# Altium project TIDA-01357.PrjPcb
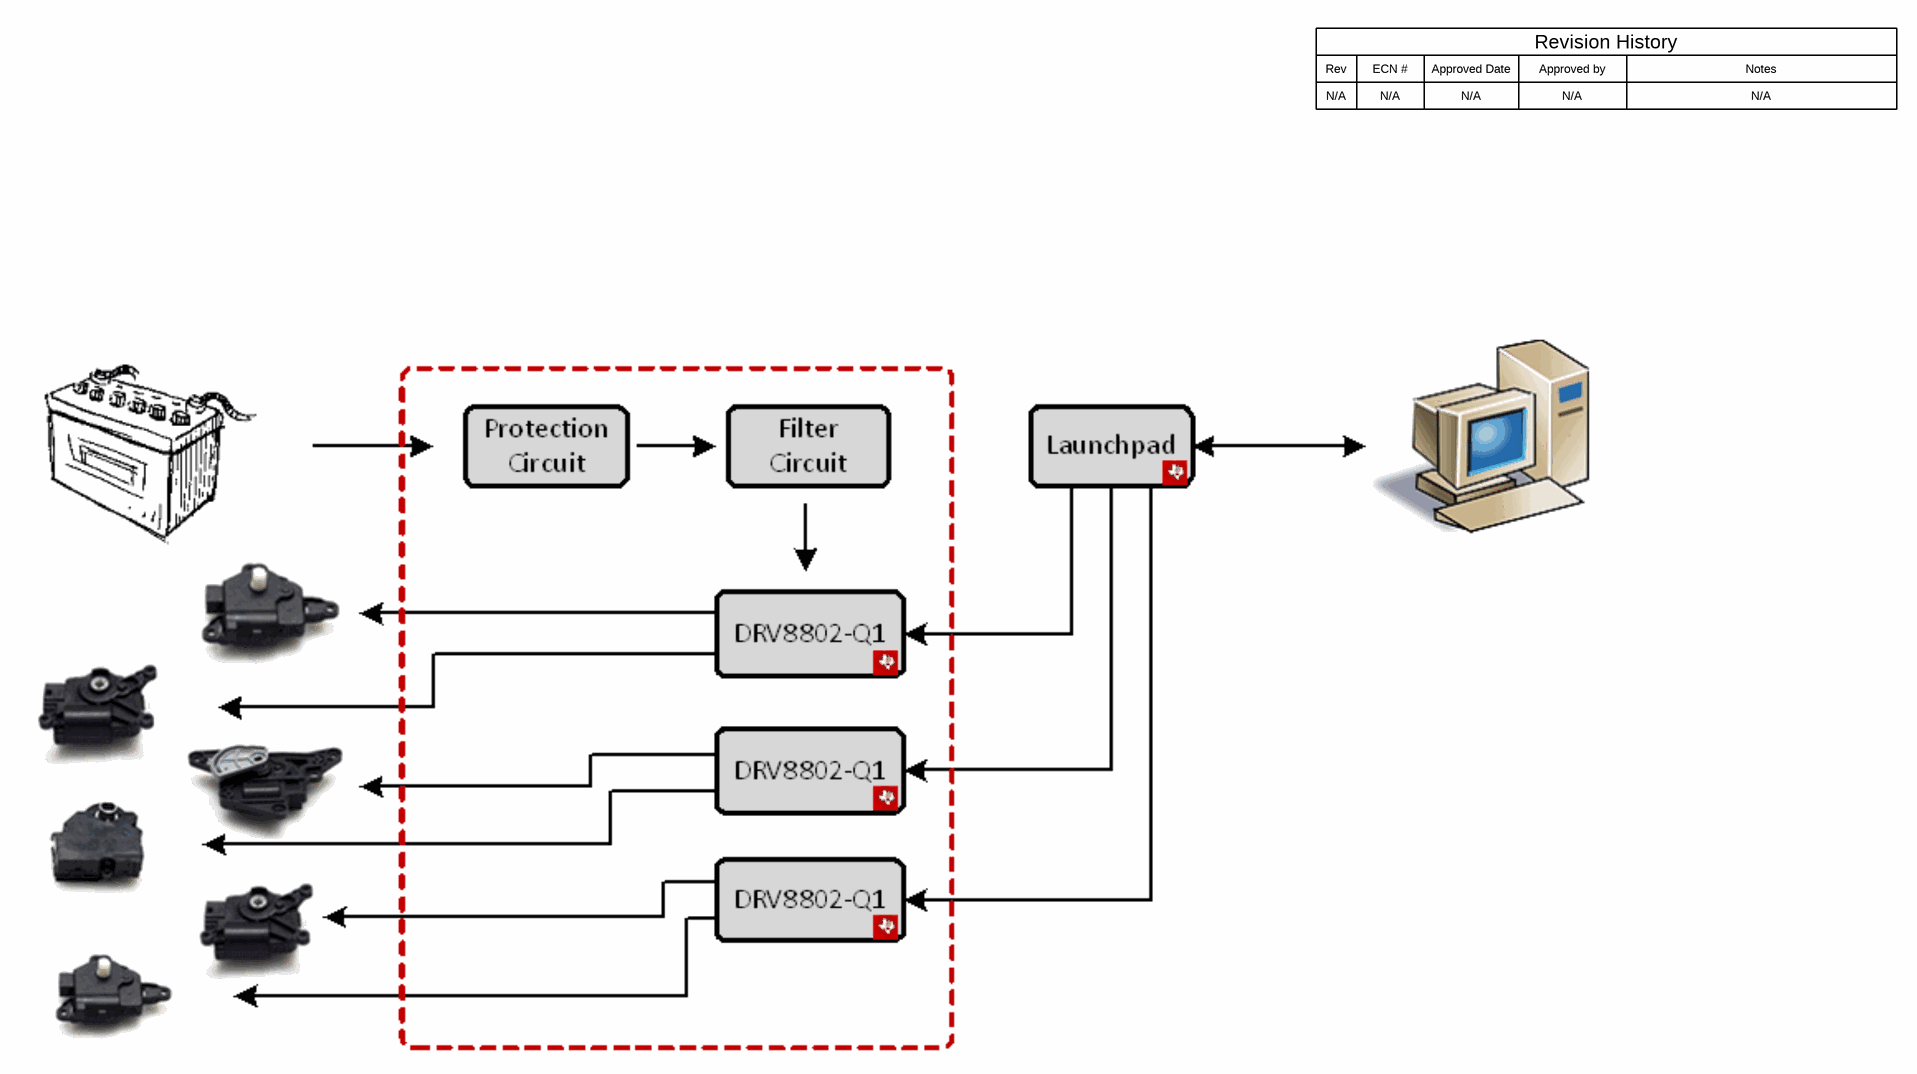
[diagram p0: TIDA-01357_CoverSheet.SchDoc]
CopyrightYear: 2016; PCB_Layout: Levan Bidzishvili; PCB_Rev: E1; PRJ_Customer: Public Release; PRJ_Engineer: Levan Bidzishvili; PRJ_Number: TIDA-01357; PRJ_Title: Automotive HVAC Multiple Flap Actuator / Damper Drivers; SCH_Rev: E1; TechSupport: http://www.ti.com/support; TID: TIDA-01357
3 sheets, 70 parts. Net scope: global (net labels, ports and power ports of the same name join across sheets).
Board file: TIDA-01357_PCB.PcbDoc
Sheets:
  TIDA-01357_CoverSheet.SchDoc
  TIDA-01357_BlankSheet.SchDoc
  TIDA-01357_EVM_Hardware.SchDoc

## Sheet TIDA-01357_CoverSheet.SchDoc
size 431 x 279 mm; Date: Not shown in title block; ApprovedBy: Not shown in title block; CheckedBy: Not shown in title block; Author: Not shown in title block; CompanyName: Not shown in title block; Engineer: Not shown in title block; Organization: Not shown in title block; Address1: Not shown in title block; Address2: Not shown in title block; Address3: Not shown in title block; Address4: Not shown in title block; DocumentNumber: 1; Revision: Use project parameter SCH_Rev; SheetNumber: 1; SheetTotal: 3; PageSetup: Record=PageOptions¦CenterHorizontal=True¦CenterVertical=True¦PrintScale=1.00¦XCorrection=1.00¦YCorrection=1.00¦PrintKind=0¦BorderSize=5000000¦LeftOffset=0¦BottomOffset=0¦Orientation=2¦PaperLength=1000¦PaperWidth=1000¦Scale=100¦PaperSource=15¦PrintQuality=600¦MediaType=1¦DitherType=10¦PaperKind=Letter¦PrintScaleMode=1

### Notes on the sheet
- Rev
- N/A
- ECN #
- Approved Date
- Approved by
- Revision History
- Notes

## Sheet TIDA-01357_BlankSheet.SchDoc
size 431 x 279 mm; Date: Not shown in title block; ApprovedBy: Not shown in title block; CheckedBy: Not shown in title block; Author: Not shown in title block; CompanyName: Not shown in title block; Engineer: Not shown in title block; Organization: Not shown in title block; Address1: Not shown in title block; Address2: Not shown in title block; Address3: Not shown in title block; Address4: Not shown in title block; DocumentNumber: 1; Revision: Use project parameter SCH_Rev; SheetNumber: 2; SheetTotal: 3; PageSetup: Record=PageOptions¦CenterHorizontal=True¦CenterVertical=True¦PrintScale=1.00¦XCorrection=1.00¦YCorrection=1.00¦PrintKind=0¦BorderSize=5000000¦LeftOffset=0¦BottomOffset=0¦Orientation=2¦PaperLength=1000¦PaperWidth=1000¦Scale=100¦PaperSource=15¦PrintQuality=600¦MediaType=1¦DitherType=10¦PaperKind=Letter¦PrintScaleMode=1
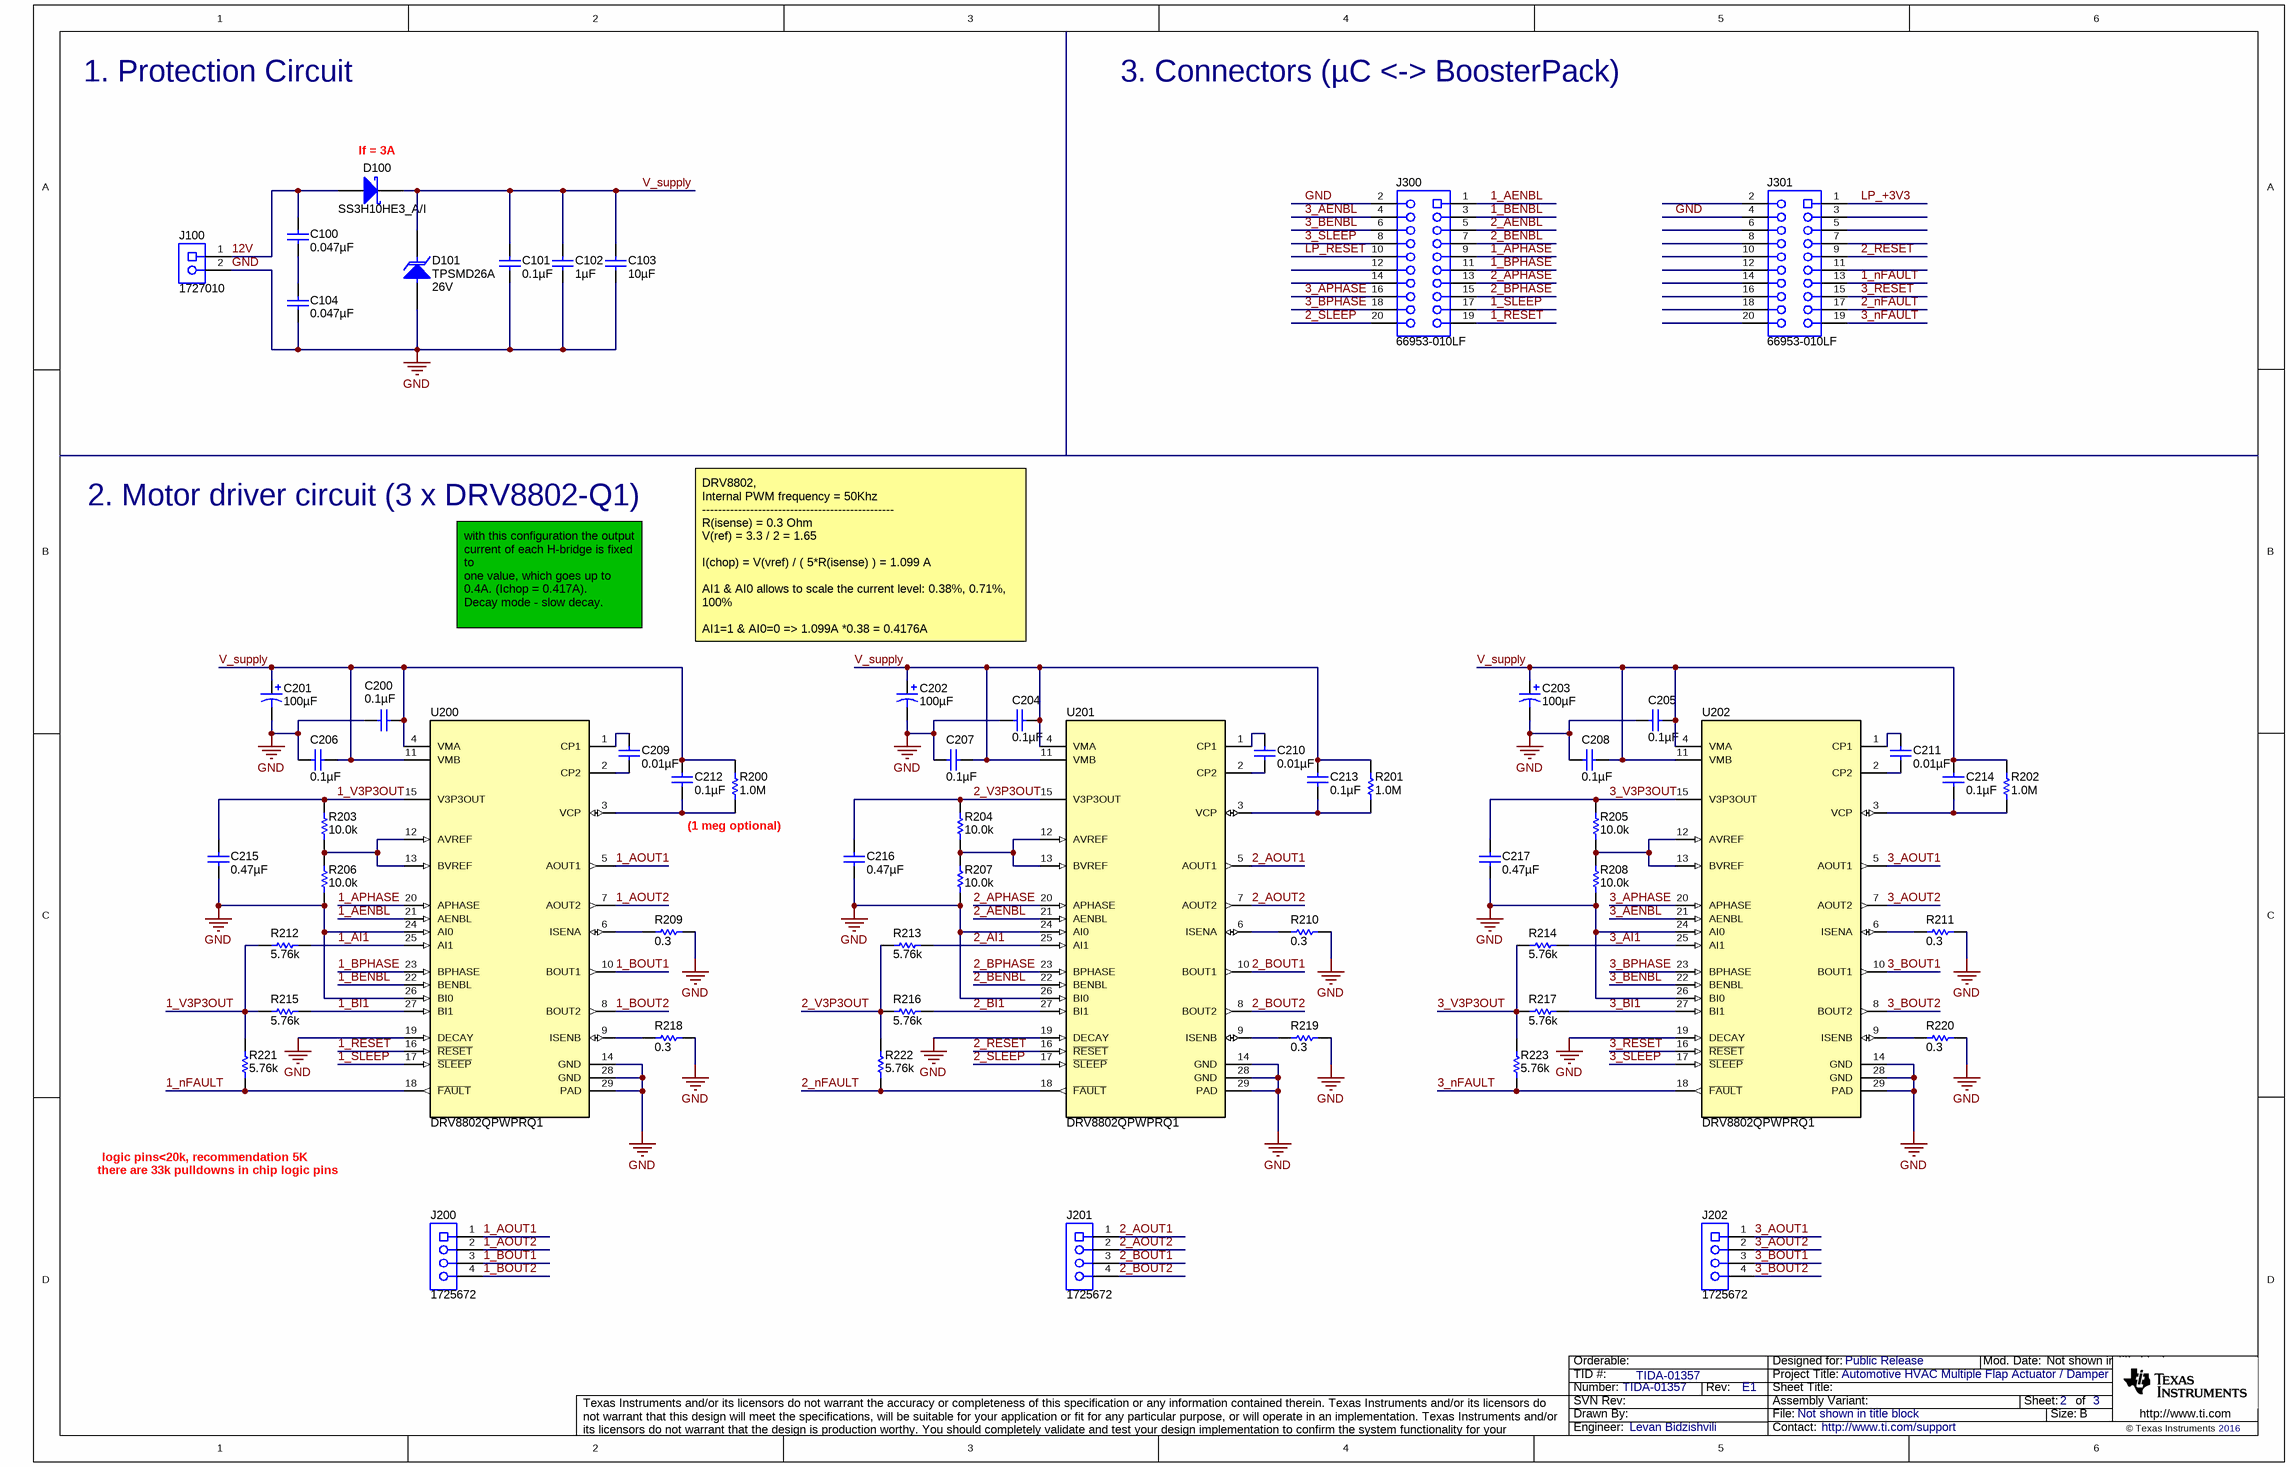
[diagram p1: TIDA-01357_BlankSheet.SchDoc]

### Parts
C100  ValueDisplayed: 0.047µF  [0805_HV]  (hidden comment: GCM21BR72A473KA37L)
C101  ValueDisplayed: 0.1µF  [0805_HV]  (hidden comment: GCM21BR71H104KA37K)
C102  ValueDisplayed: 1µF  [1206]  (hidden comment: GCM31MR71H105KA55L)
C103  ValueDisplayed: 10µF  [1206_190]  (hidden comment: CGA5L3X5R1H106K160AB)
C104  ValueDisplayed: 0.047µF  [0805_HV]  (hidden comment: GCM21BR72A473KA37L)
C200  ValueDisplayed: 0.1µF  [0805_HV]  (hidden comment: GCM21BR71H104KA37K)
C201  ValueDisplayed: 100µF  [Panasonic_D8]  (hidden comment: EEEFTH101XAP)
C202  ValueDisplayed: 100µF  [Panasonic_D8]  (hidden comment: EEEFTH101XAP)
C203  ValueDisplayed: 100µF  [Panasonic_D8]  (hidden comment: EEEFTH101XAP)
C204  ValueDisplayed: 0.1µF  [0805_HV]  (hidden comment: GCM21BR71H104KA37K)
C205  ValueDisplayed: 0.1µF  [0805_HV]  (hidden comment: GCM21BR71H104KA37K)
C206  ValueDisplayed: 0.1µF  [0805_HV]  (hidden comment: GCM21BR71H104KA37K)
C207  ValueDisplayed: 0.1µF  [0805_HV]  (hidden comment: GCM21BR71H104KA37K)
C208  ValueDisplayed: 0.1µF  [0805_HV]  (hidden comment: GCM21BR71H104KA37K)
C209  ValueDisplayed: 0.01µF  [0603]  (hidden comment: GCM188R71H103KA37D)
C210  ValueDisplayed: 0.01µF  [0603]  (hidden comment: GCM188R71H103KA37D)
C211  ValueDisplayed: 0.01µF  [0603]  (hidden comment: GCM188R71H103KA37D)
C212  ValueDisplayed: 0.1µF  [0603]  (hidden comment: GCM188R71C104KA37J)
C213  ValueDisplayed: 0.1µF  [0603]  (hidden comment: GCM188R71C104KA37J)
C214  ValueDisplayed: 0.1µF  [0603]  (hidden comment: GCM188R71C104KA37J)
C215  ValueDisplayed: 0.47µF  [0603]  (hidden comment: GCM188R71C474KA55D)
C216  ValueDisplayed: 0.47µF  [0603]  (hidden comment: GCM188R71C474KA55D)
C217  ValueDisplayed: 0.47µF  [0603]  (hidden comment: GCM188R71C474KA55D)
D100  SS3H10HE3_A/I  [SMC_265]
D101  TPSMD26A  value 26V  [SMC_265]
J100  1727010  [PhoenixConact_1727010]
J200  1725672  [Phoenix_1725672]
J201  1725672  [Phoenix_1725672]
J202  1725672  [Phoenix_1725672]
J300  66953-010LF  [FCI_66953-010LF]
J301  66953-010LF  [FCI_66953-010LF]
R200  ValueDisplayed: 1.0M  [0603]  (hidden comment: CRCW06031M00JNEA)
R201  ValueDisplayed: 1.0M  [0603]  (hidden comment: CRCW06031M00JNEA)
R202  ValueDisplayed: 1.0M  [0603]  (hidden comment: CRCW06031M00JNEA)
R203  ValueDisplayed: 10.0k  [0603]  (hidden comment: CRCW060310K0FKEA)
R204  ValueDisplayed: 10.0k  [0603]  (hidden comment: CRCW060310K0FKEA)
R205  ValueDisplayed: 10.0k  [0603]  (hidden comment: CRCW060310K0FKEA)
R206  ValueDisplayed: 10.0k  [0603]  (hidden comment: CRCW060310K0FKEA)
R207  ValueDisplayed: 10.0k  [0603]  (hidden comment: CRCW060310K0FKEA)
R208  ValueDisplayed: 10.0k  [0603]  (hidden comment: CRCW060310K0FKEA)
R209  ValueDisplayed: 0.3  [2010]  (hidden comment: CSR2010JTR300)
R210  ValueDisplayed: 0.3  [2010]  (hidden comment: CSR2010JTR300)
R211  ValueDisplayed: 0.3  [2010]  (hidden comment: CSR2010JTR300)
R212  ValueDisplayed: 5.76k  [0603]  (hidden comment: ERA-3AEB5761V)
R213  ValueDisplayed: 5.76k  [0603]  (hidden comment: ERA-3AEB5761V)
R214  ValueDisplayed: 5.76k  [0603]  (hidden comment: ERA-3AEB5761V)
R215  ValueDisplayed: 5.76k  [0603]  (hidden comment: ERA-3AEB5761V)
R216  ValueDisplayed: 5.76k  [0603]  (hidden comment: ERA-3AEB5761V)
R217  ValueDisplayed: 5.76k  [0603]  (hidden comment: ERA-3AEB5761V)
R218  ValueDisplayed: 0.3  [2010]  (hidden comment: CSR2010JTR300)
R219  ValueDisplayed: 0.3  [2010]  (hidden comment: CSR2010JTR300)
R220  ValueDisplayed: 0.3  [2010]  (hidden comment: CSR2010JTR300)
R221  ValueDisplayed: 5.76k  [0603]  (hidden comment: ERA-3AEB5761V)
R222  ValueDisplayed: 5.76k  [0603]  (hidden comment: ERA-3AEB5761V)
R223  ValueDisplayed: 5.76k  [0603]  (hidden comment: ERA-3AEB5761V)
U200  DRV8802QPWPRQ1  [PWP0028H_N]
U201  DRV8802QPWPRQ1  [PWP0028H_N]
U202  DRV8802QPWPRQ1  [PWP0028H_N]

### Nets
GND: C101.2 C102.2 C103.2 C104.2 C200.1 C201.2(-) C202.2(-) C203.2(-) C204.1 C205.2 C206.1 C207.1 C208.1 C215.2 C216.2 C217.2 D101.2(A) J100.2 J300.2 J301.4 R206.2 R207.2 R208.2 R209.2 R210.2 R211.2 R218.2 R219.2 R220.2 U200.14(GND) U200.19(DECAY) U200.24(AI0) U200.26(BI0) U200.28(GND) U200.29(PAD) U201.14(GND) U201.19(DECAY) U201.24(AI0) U201.26(BI0) U201.28(GND) U201.29(PAD) U202.14(GND) U202.19(DECAY) U202.24(AI0) U202.26(BI0) U202.28(GND) U202.29(PAD)
1_AENBL: J300.1 U200.21(AENBL)
1_AI1: R212.2 U200.25(AI1)
1_AOUT1: J200.1 U200.5(AOUT1)
1_AOUT2: J200.2 U200.7(AOUT2)
1_APHASE: J300.9 U200.20(APHASE)
1_BENBL: J300.3 U200.22(BENBL)
1_BI1: R215.2 U200.27(BI1)
1_BOUT1: J200.3 U200.10(BOUT1)
1_BOUT2: J200.4 U200.8(BOUT2)
1_BPHASE: J300.11 U200.23(BPHASE)
1_nFAULT: J301.13 R221.1 U200.18(~{FAULT})
1_RESET: J300.19 U200.16(~{RESET})
1_SLEEP: J300.17 U200.17(~{SLEEP})
1_V3P3OUT: C215.1 R203.1 R212.1 R215.1 R221.2 U200.15(V3P3OUT)
2_AENBL: J300.5 U201.21(AENBL)
2_AI1: R213.2 U201.25(AI1)
2_AOUT1: J201.1 U201.5(AOUT1)
2_AOUT2: J201.2 U201.7(AOUT2)
2_APHASE: J300.13 U201.20(APHASE)
2_BENBL: J300.7 U201.22(BENBL)
2_BI1: R216.2 U201.27(BI1)
2_BOUT1: J201.3 U201.10(BOUT1)
2_BOUT2: J201.4 U201.8(BOUT2)
2_BPHASE: J300.15 U201.23(BPHASE)
2_nFAULT: J301.17 R222.1 U201.18(~{FAULT})
2_RESET: J301.9 U201.16(~{RESET})
2_SLEEP: J300.20 U201.17(~{SLEEP})
2_V3P3OUT: C216.1 R204.1 R213.1 R216.1 R222.2 U201.15(V3P3OUT)
3_AENBL: J300.4 U202.21(AENBL)
3_AI1: R214.2 U202.25(AI1)
3_AOUT1: J202.1 U202.5(AOUT1)
3_AOUT2: J202.2 U202.7(AOUT2)
3_APHASE: J300.16 U202.20(APHASE)
3_BENBL: J300.6 U202.22(BENBL)
3_BI1: R217.2 U202.27(BI1)
3_BOUT1: J202.3 U202.10(BOUT1)
3_BOUT2: J202.4 U202.8(BOUT2)
3_BPHASE: J300.18 U202.23(BPHASE)
3_nFAULT: J301.19 R223.1 U202.18(~{FAULT})
3_RESET: J301.15 U202.16(~{RESET})
3_SLEEP: J300.8 U202.17(~{SLEEP})
3_V3P3OUT: C217.1 R205.1 R214.1 R217.1 R223.2 U202.15(V3P3OUT)
12V: C100.1 D100.2(A) J100.1
LP_+3V3: J301.1
LP_RESET: J300.10
V_supply: C101.1 C102.1 C103.1 C200.2 C201.1(+) C202.1(+) C203.1(+) C204.2 C205.1 C206.2 C207.2 C208.2 C212.1 C213.1 C214.1 D100.1(K) D101.1(K) R200.2 R201.2 R202.2 U200.4(VMA) U200.11(VMB) U201.4(VMA) U201.11(VMB) U202.4(VMA) U202.11(VMB)
NetC100_2: C100.2 C104.1
NetC209_1: C209.1 U200.1(CP1)
NetC209_2: C209.2 U200.2(CP2)
NetC210_1: C210.1 U201.1(CP1)
NetC210_2: C210.2 U201.2(CP2)
NetC211_1: C211.1 U202.1(CP1)
NetC211_2: C211.2 U202.2(CP2)
NetC212_2: C212.2 R200.1 U200.3(VCP)
NetC213_2: C213.2 R201.1 U201.3(VCP)
NetC214_2: C214.2 R202.1 U202.3(VCP)
NetR203_2: R203.2 R206.1 U200.12(AVREF) U200.13(BVREF)
NetR204_2: R204.2 R207.1 U201.12(AVREF) U201.13(BVREF)
NetR205_2: R205.2 R208.1 U202.12(AVREF) U202.13(BVREF)
NetR209_1: R209.1 U200.6(ISENA)
NetR210_1: R210.1 U201.6(ISENA)
NetR211_1: R211.1 U202.6(ISENA)
NetR218_1: R218.1 U200.9(ISENB)
NetR219_1: R219.1 U201.9(ISENB)
NetR220_1: R220.1 U202.9(ISENB)

Not connected (* = marked no-connect by the designer): J300 12 14; J301 2 3 5 6 7 8 10 11 12 14 16 18 20

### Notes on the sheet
- 1. Protection Circuit
- 3. Connectors (µC <-> BoosterPack)
- (near D100) If = 3A
- (near D100) SE30AFG VISHAY
  Surface Mount ESD Capable Rectifier AEC-Q101
- standoff voltage should be above 24V because of jump-start condition. better would be 26V
  SMAJ26CAHE3/61 VISHAY
  TPS... littlefuse
- 2. Motor driver circuit (3 x DRV8802-Q1)
- with this configuration the output current of each H-bridge is fixed to
  one value, which goes up to 0.4A. (Ichop = 0.417A).
  Decay mode - slow decay.
  Total current consumption will be 6 x 0.417A = 2.502.
  Rev.pol diode is limited up to 3A
- DRV8802,
  Internal PWM frequency = 50Khz
  ------------------------------------------------
  R(isense) = 0.3 Ohm
  V(ref) = 3.3 / 2 = 1.65
  I(chop) = V(vref) / ( 5*R(isense) ) = 1.099 A
  AI1 & AI0 allows to scale the current level: 0.38%, 0.71%, 100%
  AI1=1 & AI0=0 => 1.099A *0.38 = 0.4176A
  AI1=0 & AI0=1 => 1.099A *0.71 = 0.7802A
  AI1=0 & AI0=0 => 1.099A *1 = 1.099A
- (near C201) Requirements:
  AEC-Q200
  50V / 100uF
- (near U200) Iout=1mA
- (1 meg optional)
- logic input current levels:
  Il = ±20µA
  Ih = 100µA
- (near R221) DECAY pin tight to GND: Low Deday mode is active.
- logic pins<20k, recommendation 5K
- there are 33k pulldowns in chip logic pins

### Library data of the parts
C100 C104 = GCM21BR72A473KA37L: CAP, CERM, 0.047 µF, 100 V, +/- 10%, X7R, AEC-Q200 Grade 1, 0805; Manufacturer: MuRata; Polarized: N; CompType: Capacitor; Value: 0.047uF; U/M: EA; Cap_F: 0.000000047; Tolerance_%: 10; Value1: Unknown; VDC_V: 100; Value2: 100V; TaMin_C: -55; TaMax_C: 125; Cap_Case: 0805; SizeArea_mm2: 2.5; SizeAreaWB_mm2: 6.75; SizeX_mm: 2; SizeY_mm: 1.25; SizeZ_mm: 1.45; AEC Category: Q200; AEC Qualified: Y; AEC Grade: 1
C101 C200 C204-C208 = GCM21BR71H104KA37K: CAP, CERM, 0.1 µF, 50 V, +/- 10%, X7R, AEC-Q200 Grade 1, 0805; Manufacturer: MuRata; Polarized: N; CompType: Capacitor; Value: 0.1uF; U/M: EA; Cap_F: 0.0000001; Tolerance_%: 10; Value1: Unknown; VDC_V: 50; Value2: 50V; TaMin_C: -55; TaMax_C: 125; Cap_Case: 0805; SizeArea_mm2: 2.5; SizeAreaWB_mm2: 6.75; SizeX_mm: 2; SizeY_mm: 1.25; SizeZ_mm: 1.45; AEC Category: Q200; AEC Qualified: Y; AEC Grade: 1
C102 = GCM31MR71H105KA55L: CAP, CERM, 1 µF, 50 V, +/- 10%, X7R, AEC-Q200 Grade 1, 1206; Manufacturer: MuRata; Polarized: N; CompType: Capacitor; Value: 1uF; U/M: EA; Cap_F: 0.000001; Tolerance_%: 10; Value1: Unknown; VDC_V: 50; Value2: 50V; TaMin_C: -55; TaMax_C: 125; SizeArea_mm2: 5.12; SizeAreaWB_mm2: 10.92; SizeX_mm: 3.2; SizeY_mm: 1.6; SizeZ_mm: 1.35; AEC Category: Q200; AEC Qualified: Y; AEC Grade: 1
C103 = CGA5L3X5R1H106K160AB: CAP, CERM, 10 µF, 50 V, +/- 10%, X5R, 1206_190; Manufacturer: TDK; Polarized: N; CompType: Capacitor; Value: 10uF; U/M: EA; Cap_F: 0.00001; Tolerance_%: 10; Value1: Unknown; VDC_V: 50; Value2: 50V; TaMin_C: -55; TaMax_C: 85; Cap_Case: 1206; SizeArea_mm2: 5.12; SizeAreaWB_mm2: 10.92; SizeX_mm: 3.2; SizeY_mm: 1.6; SizeZ_mm: 1.9; AEC Category: Q200
C201-C203 = EEEFTH101XAP: CAP, AL, 100 µF, 50 V, +/- 20%, 0.34 ohm, AEC-Q200 Grade 2, SMD; Manufacturer: Panasonic; Polarized: Y; CompType: Capacitor; Value: 100uF; U/M: EA; Cap_F: 0.0001; Tolerance_%: 20; VDC_V: 50; Value2: 50V; ESR_ohm: 0.34; IRMS_A: 0.35; TaMin_C: -55; TaMax_C: 105; Cap_Case: 6.3x7.7mm; SizeAreaWB_mm2: 73.96; SizeArea_mm2: 43.56; SizeX_mm: 6.6; SizeZ_mm: 8; AEC Category: Q200; AEC Grade: 2
C209-C211 = GCM188R71H103KA37D: CAP, CERM, 0.01 µF, 50 V, +/- 10%, X7R, AEC-Q200 Grade 1, 0603; Manufacturer: MuRata; Polarized: N; CompType: Capacitor; Value: 0.01uF; U/M: EA; Cap_F: 0.00000001; Tolerance_%: 10; Value1: Unknown; VDC_V: 50; Value2: 50V; TaMin_C: -55; TaMax_C: 125; SizeArea_mm2: 1.28; SizeAreaWB_mm2: 4.68; SizeX_mm: 1.6; SizeY_mm: 0.8; SizeZ_mm: 1; AEC Category: Q200; AEC Qualified: Y
C212-C214 = GCM188R71C104KA37J: CAP, CERM, 0.1 µF, 16 V, +/- 10%, X7R, AEC-Q200 Grade 1, 0603; Manufacturer: MuRata; Polarized: N; CompType: Capacitor; Value: 0.1uF; U/M: EA; Cap_F: 0.0000001; Tolerance_%: 10; Value1: Unknown; VDC_V: 16; Value2: 16V; TaMin_C: -55; TaMax_C: 125; SizeArea_mm2: 1.28; SizeAreaWB_mm2: 4.68; SizeX_mm: 1.6; SizeY_mm: 0.8; SizeZ_mm: 1; AEC Category: Q200; AEC Qualified: Y
C215-C217 = GCM188R71C474KA55D: CAP, CERM, 0.47 µF, 16 V, +/- 10%, X7R, AEC-Q200 Grade 1, 0603; Manufacturer: MuRata; Polarized: N; CompType: Capacitor; Value: 0.47uF; U/M: EA; Cap_F: 0.00000047; Tolerance_%: 10; Value1: Unknown; VDC_V: 16; Value2: 16V; TaMin_C: -55; TaMax_C: 125; SizeArea_mm2: 1.28; SizeAreaWB_mm2: 4.68; SizeX_mm: 1.6; SizeY_mm: 0.8; SizeZ_mm: 1; AEC Category: Q200; AEC Qualified: Y
D100 = SS3H10HE3_A/I: Diode, Schottky, 100 V, 3 A, AEC-Q101, SMC; Manufacturer: Vishay-Siliconix; U/M: EA; Vf_V: 0.8; Value: 100V; Value1: 3A; Value2: 0.8V; Io_A: 3; Vr_V: 100; TJmax_C: 175; SizeAreaWB_mm2: 78.5757; SizeArea_mm2: 46.8857; SizeX_mm: 7.94; SizeY_mm: 5.905; SizeZ_mm: 2.62; AEC Category: Q101; AEC Qualified: Y
D101 = TPSMD26A: Diode, TVS, Uni, 26 V, 42.1 Vc, AEC-Q101, SMC; Manufacturer: Littelfuse; U/M: EA; Power_W: 6.5; Vr_V: 26; Value1: 6.5W; RJA_CperW: 75; SizeAreaWB_mm2: 78.5757; SizeArea_mm2: 46.8857; SizeX_mm: 7.94; SizeY_mm: 5.905; SizeZ_mm: 2.62; AEC Category: Q101; AEC Qualified: Y
J100 = 1727010: Conn Term Block, 2POS, 3.81mm, TH; Manufacturer: Phoenix Contact; SymbolCreator: a0412235; CompType: Terminal Block
J200-J202 = 1725672: Terminal Block, 4x1, 2.54 mm, Green, TH; Manufacturer: Phoenix Contact; SymbolCreator: a0411947; Pitch_mm: 2.54; Gender: Female; Row_Count: 1; Current_A: 6; Voltage_V: 125; Cert_CSA: Y
J300 J301 = 66953-010LF: Receptacle, 100mil, 10X2, Tin, TH; Manufacturer: FCI; SymbolCreator: a0412235
R200-R202 = CRCW06031M00JNEA: RES, 1.0 M, 5%, 0.1 W, 0603; Manufacturer: Vishay-Dale; CompType: Resistor; Value: 1.0Meg; Res_ohm: 1000000; Value_Code: 1M00; Tolerance_%: 5; Power_W: 0.1; Value2: 0.1W; VDC_V: 75; TempCo: 200 ppm/C; SizeArea_mm2: 1.28; SizeX_mm: 1.6; SizeY_mm: 0.8; SizeZ_mm: 1; EIA_Code: E24; U/M: EA; AEC Category: Q200
R203-R208 = CRCW060310K0FKEA: RES, 10.0 k, 1%, 0.1 W, 0603; Manufacturer: Vishay-Dale; CompType: Resistor; Value: 10.0k; Res_ohm: 10000; Value_Code: 10k0; Tolerance_%: 1; Power_W: 0.1; Value2: 0.1W; VDC_V: 75; TempCo: 100 ppm/C; SizeArea_mm2: 1.28; SizeX_mm: 1.6; SizeY_mm: 0.8; EIA_Code: E96; U/M: EA; AEC Category: Q200
R209-R211 R218-R220 = CSR2010JTR300: RES, 0.3, 5%, 1 W, 2010; Manufacturer: Stackpole Electronics Inc; CompType: Resistor; Value: 0.3; Value_Code: R300; Tolerance_%: 5; Power_W: 1; Value2: 1W; TempCo: 100 ppm/C; SizeArea_mm2: 12.5; SizeY_mm: 2.5; SizeZ_mm: 1.66; U/M: EA; AEC Category: Q200
R212-R217 R221-R223 = ERA-3AEB5761V: RES, 5.76 k, 0.1%, 0.1 W, AEC-Q200 Grade 0, 0603; Manufacturer: Panasonic; CompType: Resistor; Value: 5.76k; Res_ohm: 5760; Value_Code: 5k76; Tolerance_%: 0.1; Value2: 0.1W; VDC_V: 75; TempCo: 25 ppm/C; SizeArea_mm2: 1.28; SizeX_mm: 1.6; SizeY_mm: 0.8; SizeZ_mm: 1; EIA_Code: E192; U/M: EA; AEC Category: Q200; AEC Qualified: Y; AEC Grade: 0
U200-U202 = DRV8802QPWPRQ1: AUTOMOTIVE DC MOTOR DRIVER IC, PWP0028H (TSSOP-28); Manufacturer: Texas Instruments; SymbolCreator: a0411947; SizeArea_mm2: 62.08; SizeAreaWB_mm2: 98.28; SizeX_mm: 6.4; SizeY_mm: 9.7; SizeZ_mm: 1.2; U/M: EA

## Sheet TIDA-01357_EVM_Hardware.SchDoc
size 431 x 279 mm; Date: Not shown in title block; ApprovedBy: Not shown in title block; CheckedBy: Not shown in title block; Author: Not shown in title block; CompanyName: Not shown in title block; Engineer: Not shown in title block; Organization: Not shown in title block; Address1: Not shown in title block; Address2: Not shown in title block; Address3: Not shown in title block; Address4: Not shown in title block; DocumentNumber: 1; Revision: Use project parameter SCH_Rev; SheetNumber: 3; SheetTotal: 3; PageSetup: Record=PageOptions¦CenterHorizontal=True¦CenterVertical=True¦PrintScale=1.00¦XCorrection=1.00¦YCorrection=1.00¦PrintKind=0¦BorderSize=5000000¦LeftOffset=0¦BottomOffset=0¦Orientation=2¦PaperLength=1000¦PaperWidth=1000¦Scale=100¦PaperSource=15¦PrintQuality=600¦MediaType=1¦DitherType=10¦PaperKind=Letter¦PrintScaleMode=1
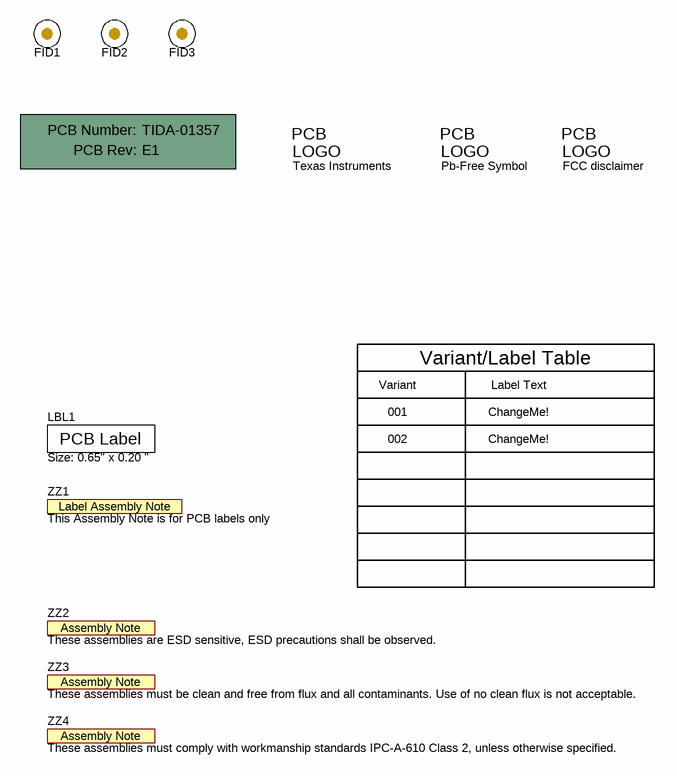
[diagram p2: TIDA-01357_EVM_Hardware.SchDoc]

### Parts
!PCB  Printed Circuit Board  (value not drawn)  (mechanical)
FID1  Fiducial  [Fiducial10-20]  (value not drawn)
FID2  Fiducial  [Fiducial10-20]  (value not drawn)
FID3  Fiducial  [Fiducial10-20]  (value not drawn)
LBL1  Size: 0.65" x 0.20 "  [Label_650x200]
Logo1  Texas Instruments  [TI_Symbol_Overlay_Small]  (no BOM)
Logo2  Pb-Free Symbol  [Pb-Free_Overlay_Small]  (no BOM)
Logo3  FCC disclaimer  [FCC_disclaimer]  (no BOM)
ZZ1  This Assembly Note is for PCB labels only  [AssemblyNoteLabel]  (no BOM)
ZZ2  These assemblies are ESD sensitive, ESD precautions shall be observed.  [AssemblyNote]  (no BOM)
ZZ3  These assemblies must be clean and free from flux and all contaminants. Use of no clean flux is not acceptable.  [AssemblyNote]  (no BOM)
ZZ4  These assemblies must comply with workmanship standards IPC-A-610 Class 2, unless otherwise specified.  [AssemblyNote]  (no BOM)

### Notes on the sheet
- Variant
- Variant/Label Table
- Label Text
- 001
- 002
- ChangeMe!

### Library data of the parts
!PCB = PCB: Manufacturer: Any; PartNumber: TIDA-01357; SymbolCreator: a0412235
FID1-FID3 = Fiducial: Fiducial mark.  There is nothing to buy or mount.; SymbolCreator: codlsc
LBL1 = THT-14-423-10: Thermal Transfer Printable Labels, 0.650" W x 0.200" H - 10,000 per roll; Manufacturer: Brady; SymbolCreator: a0412235; CompType: Label
Logo1 = TI_Logo: Texas Instrument Corporate Signature; SymbolCreator: codlsc
Logo2 = Pb-Free: SymbolCreator: a0412235
Logo3 = FCC_disclaimer: SymbolCreator: codlsc
ZZ1 = AssemblyNoteLabel: SymbolCreator: a0412235
ZZ2-ZZ4 = AssemblyNote: SymbolCreator: codlsc

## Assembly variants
001: not fitted FID1 FID2 FID3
